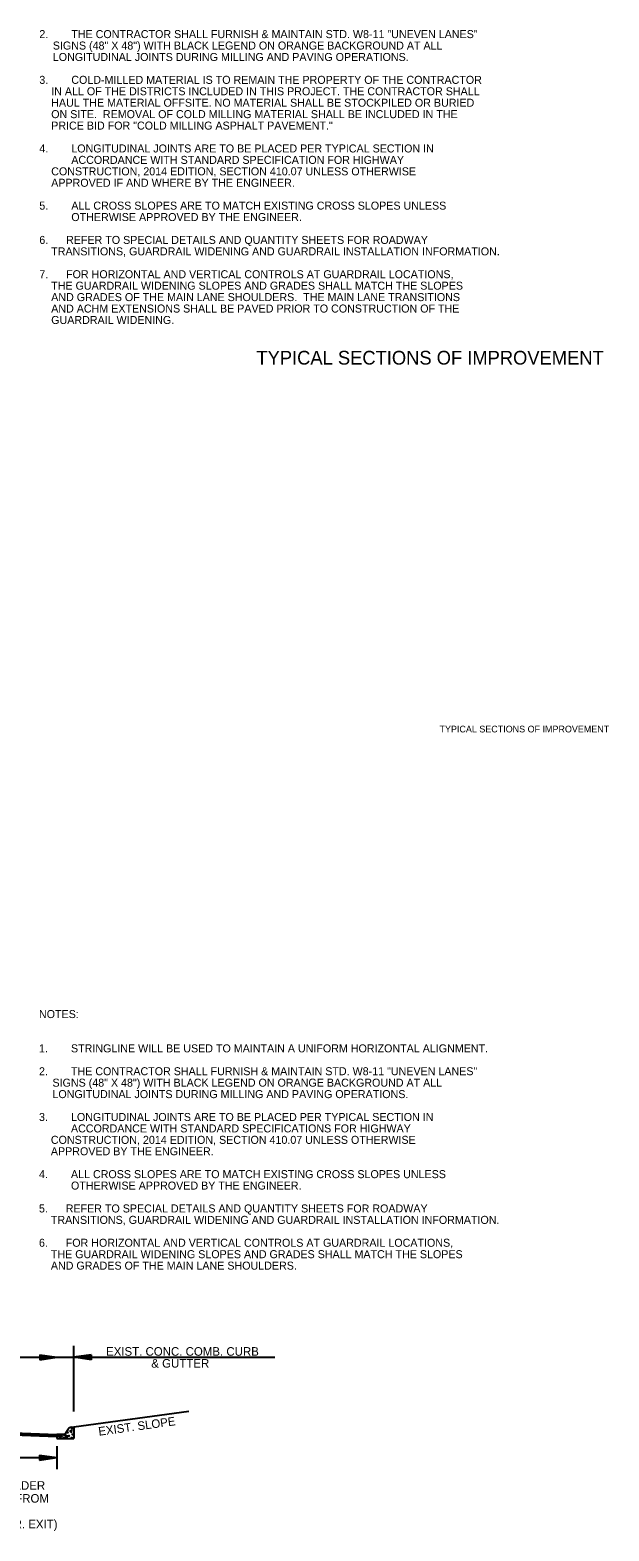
# Model space of a CAD drawing. Extents: x 542112 to 1930787, y -1968972 to 596640.
# Drawn here: x 545248 to 545755, y -1953261 to -1951948 of the extents above; entities that cross this region are included whole.
import ezdxf

# ---------------------------------------------------------------- set-up
doc = ezdxf.new("R2010")
doc.units = 0
for name, color, linetype in [('R_Border', 7, 'Continuous'), ('R_Border Notes', 7, 'Continuous'), ('R_Border Prem', 7, 'Continuous'), ('R_Draft', 7, 'Continuous')]:
    doc.layers.add(name, color=color, linetype=linetype)

msp = doc.modelspace()

# ---------------------------------------------------------------- linework, layer by layer
at = {"layer": 'R_Draft'}
for p, q in [((545286.8, -1953156.2), (545286.8, -1953098.9)), ((545151.8, -1953108.8), (545271.8, -1953108.8)), ((545256.8, -1953106.6), (545271.8, -1953108.8)), ((545256.8, -1953106.6), (545256.8, -1953111.1)), ((545256.8, -1953106.9), (545269.3, -1953108.8)), ((545256.8, -1953107.3), (545266.7, -1953108.8)), ((545256.8, -1953107.7), (545264.2, -1953108.8)), ((545256.8, -1953108.1), (545261.6, -1953108.8)), ((545256.8, -1953108.5), (545259.1, -1953108.8)), ((545256.8, -1953111.1), (545271.8, -1953108.8)), ((545256.8, -1953109.5), (545261.6, -1953108.8)), ((545256.8, -1953110.3), (545266.7, -1953108.8)), ((545256.8, -1953110.7), (545269.3, -1953108.8)), ((545256.8, -1953109.9), (545264.2, -1953108.8)), ((545256.8, -1953109.2), (545259.1, -1953108.8)), ((545271.8, -1953108.8), (545462.6, -1953108.8)), ((545301.8, -1953106.6), (545286.8, -1953108.8)), ((545301.8, -1953111.1), (545286.8, -1953108.8)), ((545301.8, -1953106.9), (545289.3, -1953108.8)), ((545301.8, -1953110.7), (545289.3, -1953108.8)), ((545301.8, -1953107.3), (545291.9, -1953108.8)), ((545301.8, -1953110.3), (545291.9, -1953108.8)), ((545301.8, -1953107.7), (545294.4, -1953108.8)), ((545301.8, -1953109.9), (545294.4, -1953108.8)), ((545301.8, -1953108.1), (545296.9, -1953108.8)), ((545301.8, -1953109.5), (545296.9, -1953108.8)), ((545301.8, -1953108.5), (545299.4, -1953108.8)), ((545301.8, -1953109.2), (545299.4, -1953108.8)), ((545301.8, -1953106.6), (545301.8, -1953111.1)), ((545387.3, -1953156.3), (545286.8, -1953170.1)), ((545151.8, -1953171.7), (545271.8, -1953176.5)), ((545151.8, -1953172), (545271.8, -1953176.8)), ((545151.8, -1953172.3), (545271.8, -1953177.1)), ((545151.8, -1953172.6), (545271.8, -1953177.4)), ((545151.8, -1953172.9), (545271.8, -1953177.7)), ((545151.8, -1953173.2), (545271.8, -1953178)), ((545151.8, -1953173.3), (545271.8, -1953178.1)), ((545278.7, -1953176.5), (545271.8, -1953176.5)), ((545271.8, -1953176.5), (545271.8, -1953180)), ((545281.8, -1953171.6), (545278.7, -1953176.5)), ((545284.6, -1953170.1), (545286.8, -1953170.1)), ((545286.8, -1953170.1), (545286.8, -1953180)), ((545271.8, -1953180), (545286.8, -1953180)), ((545271.8, -1953186.7), (545271.8, -1953206.7)), ((544491.8, -1953196.6), (545271.8, -1953196.6)), ((545256.7, -1953194.4), (545271.7, -1953196.6)), ((545256.7, -1953194.4), (545256.7, -1953198.9)), ((545256.7, -1953194.8), (545269.2, -1953196.6)), ((545256.7, -1953195.1), (545266.7, -1953196.6)), ((545256.7, -1953195.5), (545264.2, -1953196.6)), ((545256.7, -1953195.9), (545261.6, -1953196.6)), ((545256.7, -1953196.3), (545259.1, -1953196.6)), ((545256.7, -1953198.9), (545271.7, -1953196.6)), ((545256.7, -1953197.4), (545261.6, -1953196.6)), ((545256.7, -1953198.1), (545266.7, -1953196.6)), ((545256.7, -1953198.5), (545269.2, -1953196.6)), ((545256.7, -1953197.7), (545264.2, -1953196.6)), ((545256.7, -1953197), (545259.1, -1953196.6))]:
    msp.add_line(p, q, dxfattribs=at)
for points in [[(545274.4, -1953179.8), (545275.5, -1953178.1), (545273.7, -1953177.7), (545274.4, -1953179.6)], [(545280, -1953179.5), (545281.1, -1953177.7), (545279.4, -1953177.4), (545280, -1953179.3)], [(545282.8, -1953173.5), (545284.6, -1953174.7), (545285, -1953172.9), (545283.1, -1953173.5)]]:
    msp.add_lwpolyline(points, dxfattribs=at)
for centre in [(545273.1, -1953177.6), (545276, -1953177.8), (545278.4, -1953177), (545281.3, -1953174.7), (545282.5, -1953177.5), (545285.2, -1953171.2), (545285.8, -1953176.3), (545277.9, -1953179.2), (545285, -1953179.3)]:
    msp.add_circle(centre, 0.339, dxfattribs=at)
msp.add_arc((545284.5, -1953173.3), 3.26, 88.8804, 147.7244, dxfattribs=at)

# ---------------------------------------------------------------- texts
at = {"layer": 'R_Border'}
msp.add_text('TYPICAL SECTIONS OF IMPROVEMENT', height=12, rotation=360, dxfattribs=at).set_placement((545446.5, -1952240.7))
at = {"layer": 'R_Border Notes'}
for s, p in [('2.', (545256.5, -1951955.2)), ('    SIGNS (48" X 48") WITH BLACK LEGEND ON ORANGE BACKGROUND AT ALL ', (545257.9, -1951965.2)), ('THE CONTRACTOR SHALL FURNISH & MAINTAIN STD. W8-11 "UNEVEN LANES" ', (545284.5, -1951955.2)), ('    LONGITUDINAL JOINTS DURING MILLING AND PAVING OPERATIONS.', (545257.9, -1951975.2)), ('3.', (545256.5, -1951995.2)), ('COLD-MILLED MATERIAL IS TO REMAIN THE PROPERTY OF THE CONTRACTOR', (545284.5, -1951995.2)), ('    HAUL THE MATERIAL OFFSITE. NO MATERIAL SHALL BE STOCKPILED OR BURIED', (545256.5, -1952015.2)), ('    IN ALL OF THE DISTRICTS INCLUDED IN THIS PROJECT. THE CONTRACTOR SHALL', (545256.5, -1952005.2)), ('    ON SITE.  REMOVAL OF COLD MILLING MATERIAL SHALL BE INCLUDED IN THE', (545256.5, -1952025.2)), ('    PRICE BID FOR "COLD MILLING ASPHALT PAVEMENT."', (545256.5, -1952035.2)), ('4.', (545256.5, -1952055.2)), ('LONGITUDINAL JOINTS ARE TO BE PLACED PER TYPICAL SECTION IN ', (545284.5, -1952055.2)), ('ACCORDANCE WITH STANDARD SPECIFICATION FOR HIGHWAY', (545284.5, -1952065.2)), ('    CONSTRUCTION, 2014 EDITION, SECTION 410.07 UNLESS OTHERWISE', (545256.5, -1952075.2)), ('    APPROVED IF AND WHERE BY THE ENGINEER.', (545256.5, -1952085.2)), ('5.', (545256.5, -1952105.2)), ('ALL CROSS SLOPES ARE TO MATCH EXISTING CROSS SLOPES UNLESS ', (545284.5, -1952105.2)), ('OTHERWISE APPROVED BY THE ENGINEER.', (545284.5, -1952115.2)), ('6.      REFER TO SPECIAL DETAILS AND QUANTITY SHEETS FOR ROADWAY', (545256.5, -1952135.2)), ('    TRANSITIONS, GUARDRAIL WIDENING AND GUARDRAIL INSTALLATION INFORMATION.', (545256.5, -1952145.2)), ('7.      FOR HORIZONTAL AND VERTICAL CONTROLS AT GUARDRAIL LOCATIONS,', (545256.5, -1952165.2)), ('    AND GRADES OF THE MAIN LANE SHOULDERS.  THE MAIN LANE TRANSITIONS', (545256.5, -1952185.2)), ('    THE GUARDRAIL WIDENING SLOPES AND GRADES SHALL MATCH THE SLOPES', (545256.5, -1952175.2)), ('    AND ACHM EXTENSIONS SHALL BE PAVED PRIOR TO CONSTRUCTION OF THE', (545256.5, -1952195.2)), ('    GUARDRAIL WIDENING.', (545256.5, -1952205.2)), ('NOTES: ', (545256.2, -1952812.2)), ('1.', (545256.2, -1952842.2)), ('STRINGLINE WILL BE USED TO MAINTAIN A UNIFORM HORIZONTAL ALIGNMENT.', (545284.2, -1952842.2)), ('2.', (545256.2, -1952862.2)), ('THE CONTRACTOR SHALL FURNISH & MAINTAIN STD. W8-11 "UNEVEN LANES" ', (545284.2, -1952862.2)), ('    SIGNS (48" X 48") WITH BLACK LEGEND ON ORANGE BACKGROUND AT ALL ', (545257.6, -1952872.2)), ('    LONGITUDINAL JOINTS DURING MILLING AND PAVING OPERATIONS.', (545257.6, -1952882.2)), ('3.', (545256.2, -1952902.2)), ('LONGITUDINAL JOINTS ARE TO BE PLACED PER TYPICAL SECTION IN ', (545284.2, -1952902.2)), ('    CONSTRUCTION, 2014 EDITION, SECTION 410.07 UNLESS OTHERWISE', (545256.2, -1952922.2)), ('ACCORDANCE WITH STANDARD SPECIFICATIONS FOR HIGHWAY', (545284.2, -1952912.2)), ('    APPROVED BY THE ENGINEER.', (545256.2, -1952932.2)), ('4.', (545256.2, -1952952.2)), ('ALL CROSS SLOPES ARE TO MATCH EXISTING CROSS SLOPES UNLESS ', (545284.2, -1952952.2)), ('OTHERWISE APPROVED BY THE ENGINEER.', (545284.2, -1952962.2)), ('5.      REFER TO SPECIAL DETAILS AND QUANTITY SHEETS FOR ROADWAY', (545256.2, -1952982.2)), ('    TRANSITIONS, GUARDRAIL WIDENING AND GUARDRAIL INSTALLATION INFORMATION.', (545256.2, -1952992.2)), ('6.      FOR HORIZONTAL AND VERTICAL CONTROLS AT GUARDRAIL LOCATIONS,', (545256.2, -1953012.2)), ('    THE GUARDRAIL WIDENING SLOPES AND GRADES SHALL MATCH THE SLOPES', (545256.2, -1953022.2)), ('    AND GRADES OF THE MAIN LANE SHOULDERS.  ', (545256.2, -1953032.2))]:
    msp.add_text(s, height=7, dxfattribs=at).set_placement(p)
at = {"layer": 'R_Border Prem'}
msp.add_text('TYPICAL SECTIONS OF IMPROVEMENT', height=5.862, rotation=360, dxfattribs=at).set_placement((545606.8, -1952562.4))
at = {"layer": 'R_Draft'}
for s, p in [('EXIST. CONC. COMB. CURB', (545314.9, -1953107.5)), ('& GUTTER ', (545354.5, -1953117.9)), (' **RIGHT SHOULDER', (545161.3, -1953224.7)), ('TRANSITIONS FROM ', (545165.2, -1953236)), ('(CONC. PVMT. - BR. EXIT)', (545149.3, -1953258.5))]:
    msp.add_text(s, height=7.5, dxfattribs=at).set_placement(p)
msp.add_text('EXIST. SLOPE', height=7.5, rotation=7.8318, dxfattribs=at).set_placement((545308.7, -1953177.5))

doc.saveas('drawing.dxf')
